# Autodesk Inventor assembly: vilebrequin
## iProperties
Shininess: 64.0
Length Units: 11269
Angle Units: 11279
Time Units: 11290
Mass Units: 11283
Length Display Precision: 3
Angle Display Precision: 2
Compacted: True
Created: 2006-01
Part Number: vilebrequin
Document SubType Name: Assembly
Designer: riri
Density: 0.0
Volumn: 0.0
Area: 0.0
PropertySet Name: Model Information
Control State: 0
Master: False
Checked Out: False
Author: riri
